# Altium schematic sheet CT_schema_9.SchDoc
size 405 x 220 mm
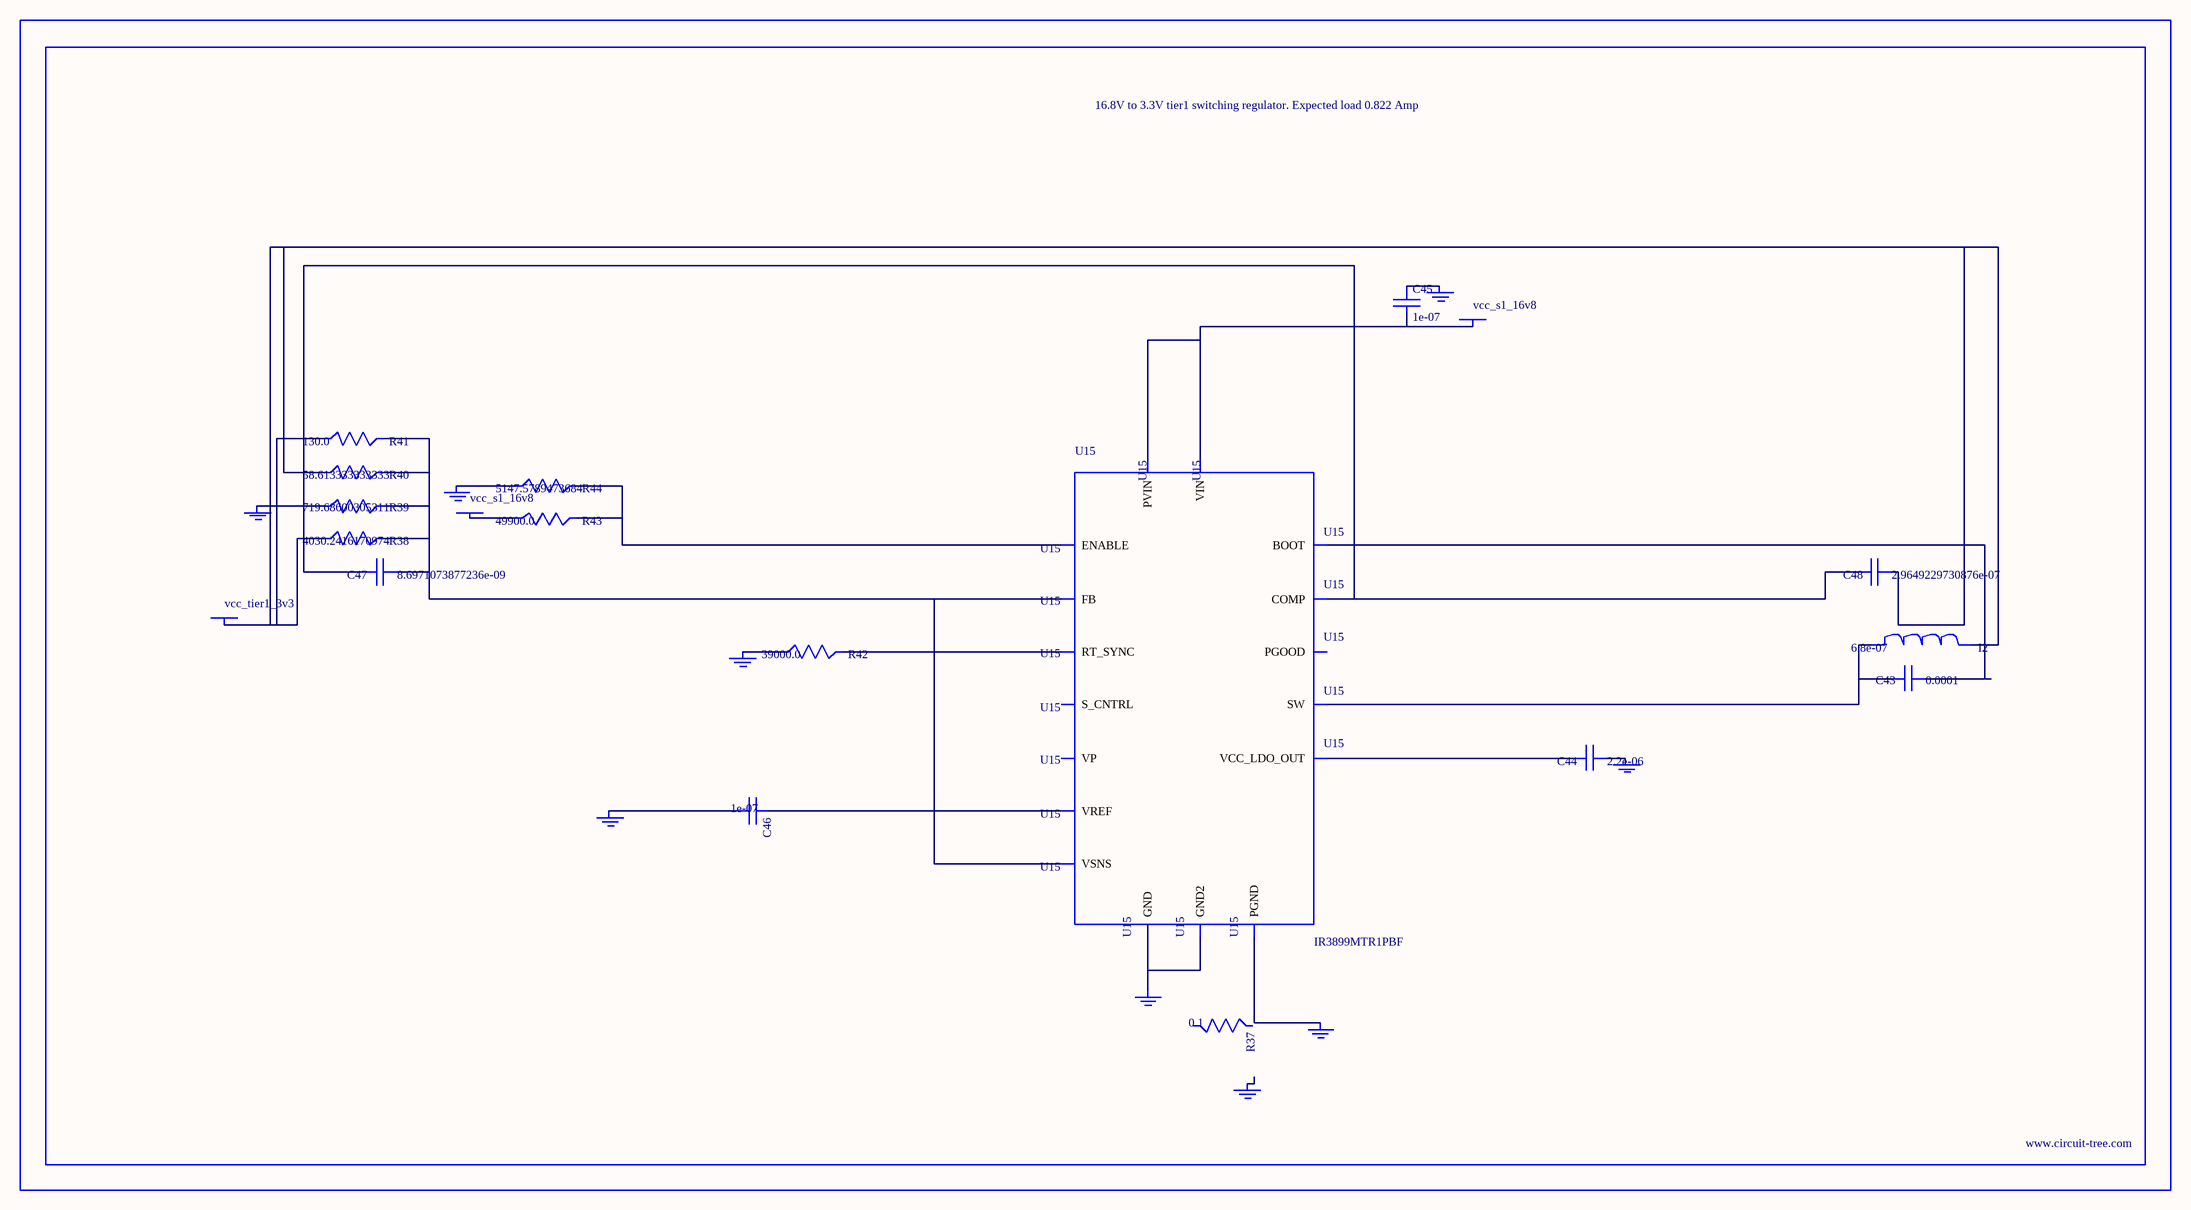
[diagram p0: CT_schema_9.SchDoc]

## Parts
BORDER8  (no value)
C43  0.0001  [C1210]
C44  2.2e-06  [C0603]
C45  1e-07  [C0402]
C46  1e-07  [C0402]
C47  8.6971073877236e-09  [R0603]
C48  2.9649229730876e-07  [R0603]
GND_INSTANCE_8_0  (no value)
GND_INSTANCE_8_1  (no value)
GND_INSTANCE_8_2  (no value)
GND_INSTANCE_8_3  (no value)
GND_INSTANCE_8_4  (no value)
GND_INSTANCE_8_5  (no value)
GND_INSTANCE_8_6  (no value)
GND_INSTANCE_8_7  (no value)
GND_INSTANCE_8_8  (no value)
I2  6.8e-07  [IND25X25CZ]
POWER_INSTANCE_8_0  vcc_s1_16v8
POWER_INSTANCE_8_1  vcc_s1_16v8
POWER_INSTANCE_8_2  vcc_tier1_3v3
R37  0.1  [R0603]
R38  4030.2416170974  [R0603]
R39  719.68600305311  [R0603]
R40  58.613333333333  [R0603]
R41  130.0  [R0603]
R42  39000.0  [R0603]
R43  49900.0  [R0603]
R44  5147.5789473684  [R0603]
U15  IR3899MTR1PBF  [IR3899MTR1PBF]

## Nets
NetC43_1: C43.1 U15.14(BOOT)
NetC43_2: C43.2 I2.1 U15.12(SW)
NetC44_1: C44.1 GND_INSTANCE_8_4.0(GND)
NetC44_2: C44.2 U15.10(VCC_LDO_OUT)
NetC45_1: C45.1 GND_INSTANCE_8_3.0(GND)
NetC45_2: C45.2 POWER_INSTANCE_8_0.0(PWR) U15.9(VIN) U15.13(PVIN)
NetC46_1: C46.1 U15.2(VREF)
NetC46_2: C46.2 GND_INSTANCE_8_1.0(GND)
NetC47_1: C47.1 R38.2 R39.2 R40.2 R41.2 U15.1(FB) U15.8(VSNS)
NetC47_2: C47.2 C48.2 U15.3(COMP)
NetC48_1: C48.1 I2.2 POWER_INSTANCE_8_2.0(PWR) R38.1 R40.1 R41.1
NetGND_INSTANCE_8_0_0: GND_INSTANCE_8_0.0(GND) R39.1
NetGND_INSTANCE_8_2_0: GND_INSTANCE_8_2.0(GND) R42.1
NetGND_INSTANCE_8_6_0: GND_INSTANCE_8_6.0(GND) U15.11(PGND)
NetGND_INSTANCE_8_7_0: GND_INSTANCE_8_7.0(GND) R44.1
NetGND_INSTANCE_8_8_0: GND_INSTANCE_8_8.0(GND) U15.4(GND) U15.17(GND2)
NetPOWER_INSTANCE_8_1_0: POWER_INSTANCE_8_1.0(PWR) R43.1
NetR42_2: R42.2 U15.5(RT_SYNC)
NetR43_2: R43.2 R44.2 U15.15(ENABLE)

Not connected (* = marked no-connect by the designer): GND_INSTANCE_8_5 0(GND); R37 1 2; U15 6(S_CNTRL) 7(PGOOD) 16(VP)

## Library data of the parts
BORDER8 = BORDER_PAGE8
C43 = GRM32ER61A107ME20L
C44 = C0603C225K8RACTU
C45 C46 = C0402C104K3RACTU
C47 = C47
C48 = C48
GND_INSTANCE_8_0-GND_INSTANCE_8_8 = GND
I2 = IHLP2525CZERR68M01
POWER_INSTANCE_8_0-POWER_INSTANCE_8_2 = PWR
R37 = ERJ-3RSFR10V
R38 = R38
R39 = R39
R40 = R40
R41 = RC0603JR-07130RL
R42 = RC0603JR-0739KL
R43 = RC0603FR-0749K9
R44 = R44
